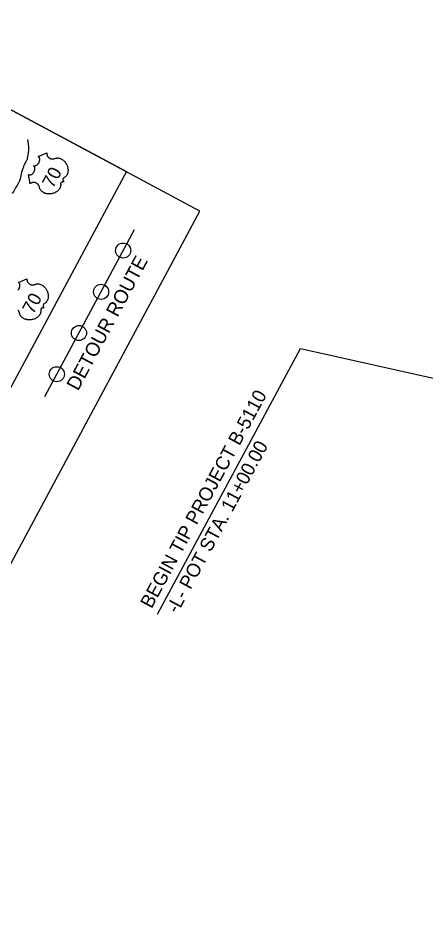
# Model space of a CAD drawing. Extents: x 1376167 to 1379209, y 761324 to 763997.
# Drawn here: x 1376772.1 to 1376981.7, y 762547.7 to 763014.5 of the extents above; entities that cross this region are included whole.
import ezdxf

# ---------------------------------------------------------------- set-up
doc = ezdxf.new("R2010")
doc.units = 0
for name, color, linetype in [('Default', 7, 'Continuous'), ('Old_Level_1', 7, 'Continuous'), ('Prop DSN Text', 7, 'Continuous')]:
    doc.layers.add(name, color=color, linetype=linetype)

msp = doc.modelspace()

# ---------------------------------------------------------------- linework, layer by layer
at = {"layer": 'Default'}
for points in [[(1376769.23, 762924.3), (1376769.71, 762925.09), (1376770.16, 762925.99), (1376770.78, 762927.08), (1376771.24, 762927.77), (1376772.3, 762929.6), (1376773, 762931.02), (1376773.32, 762931.96), (1376774.06, 762935.28), (1376774.5, 762936.86), (1376774.93, 762938.19), (1376775.09, 762938.63), (1376775.39, 762939.28), (1376776.44, 762941.22), (1376776.84, 762942.22), (1376776.93, 762942.61), (1376777.01, 762943.15), (1376777.33, 762945.03), (1376777.55, 762946.64), (1376777.51, 762948.32), (1376777.32, 762949.87), (1376777.12, 762952.07)], [(1376771.98, 762874.62), (1376772.11, 762874.77), (1376772.23, 762874.93), (1376772.35, 762875.09), (1376772.45, 762875.26), (1376772.54, 762875.4), (1376772.63, 762875.58), (1376772.71, 762875.75), (1376772.78, 762875.92), (1376772.85, 762876.13), (1376772.89, 762876.29), (1376772.95, 762876.52), (1376772.98, 762876.73), (1376772.99, 762876.92), (1376773, 762877.18), (1376772.98, 762877.4), (1376772.95, 762877.57), (1376772.9, 762877.78), (1376772.81, 762878), (1376772.74, 762878.14), (1376772.65, 762878.26), (1376772.56, 762878.38), (1376772.44, 762878.48), (1376772.34, 762878.56), (1376772.24, 762878.61), (1376776.6, 762880.49), (1376776.58, 762880.39), (1376776.58, 762880.17), (1376776.58, 762879.98), (1376776.62, 762879.67), (1376776.66, 762879.53), (1376776.69, 762879.39), (1376776.74, 762879.25), (1376776.79, 762879.12), (1376776.87, 762878.95), (1376776.96, 762878.8), (1376777.06, 762878.64), (1376777.15, 762878.51), (1376777.36, 762878.27), (1376777.5, 762878.13), (1376777.62, 762878.03), (1376777.9, 762877.83), (1376778.03, 762877.75), (1376778.17, 762877.67), (1376778.32, 762877.6), (1376778.46, 762877.54), (1376778.62, 762877.49), (1376778.76, 762877.44), (1376778.94, 762877.4), (1376779.15, 762877.36), (1376779.36, 762877.34), (1376779.73, 762877.34), (1376780.12, 762877.37), (1376780.36, 762877.42), (1376780.57, 762877.48), (1376780.85, 762877.59), (1376781, 762877.65), (1376781.19, 762877.71), (1376781.54, 762877.79), (1376781.7, 762877.81), (1376781.87, 762877.83), (1376782.04, 762877.83), (1376782.22, 762877.84), (1376782.37, 762877.83), (1376782.71, 762877.8), (1376783.03, 762877.74), (1376783.19, 762877.7), (1376783.55, 762877.59), (1376783.72, 762877.53), (1376784.04, 762877.38), (1376784.42, 762877.18), (1376784.77, 762876.96), (1376785.15, 762876.67), (1376785.37, 762876.48), (1376785.62, 762876.23), (1376785.82, 762876.02), (1376786.12, 762875.67), (1376786.32, 762875.39), (1376786.54, 762875.05), (1376786.67, 762874.83), (1376786.8, 762874.58), (1376786.94, 762874.28), (1376787.09, 762873.95), (1376787.22, 762873.57), (1376787.31, 762873.27), (1376787.4, 762872.89), (1376787.45, 762872.67), (1376787.5, 762872.36), (1376787.54, 762871.95), (1376787.55, 762871.56), (1376787.54, 762871.24), (1376787.52, 762870.96), (1376787.47, 762870.61), (1376787.35, 762870.06), (1376787.29, 762869.87), (1376787.21, 762869.64), (1376787.12, 762869.44), (1376787.03, 762869.24), (1376786.9, 762868.99), (1376786.74, 762868.74), (1376786.58, 762868.52), (1376786.39, 762868.3), (1376786.18, 762868.08), (1376785.96, 762867.9), (1376785.71, 762867.72), (1376785.24, 762867.45), (1376785.12, 762867.37), (1376785.06, 762867.31), (1376784.97, 762867.16), (1376784.93, 762867), (1376784.9, 762866.81), (1376784.9, 762866.7), (1376784.92, 762866.53), (1376784.94, 762866.4), (1376784.99, 762866.23), (1376785.04, 762866.11), (1376785.07, 762866.01), (1376785.19, 762865.8), (1376785.26, 762865.72), (1376785.34, 762865.62), (1376785.48, 762865.49), (1376785.25, 762865.55), (1376785.09, 762865.56), (1376784.93, 762865.55), (1376784.79, 762865.54), (1376784.6, 762865.49), (1376784.45, 762865.44), (1376784.28, 762865.37), (1376784.13, 762865.29), (1376784.02, 762865.21), (1376783.93, 762865.13), (1376783.84, 762865.03), (1376783.78, 762864.94), (1376783.74, 762864.86), (1376783.71, 762864.74), (1376783.73, 762864.53), (1376783.75, 762864.34), (1376783.77, 762864.14), (1376783.77, 762863.9), (1376783.76, 762863.74), (1376783.73, 762863.55), (1376783.7, 762863.33), (1376783.64, 762863.1), (1376783.57, 762862.87), (1376783.5, 762862.67), (1376783.41, 762862.47), (1376783.33, 762862.29), (1376783.23, 762862.11), (1376783.12, 762861.94), (1376783, 762861.76), (1376782.83, 762861.53), (1376782.67, 762861.35), (1376782.5, 762861.16), (1376782.31, 762860.98), (1376782.09, 762860.79), (1376781.8, 762860.56), (1376781.59, 762860.41), (1376781.22, 762860.19), (1376780.75, 762859.95), (1376780.37, 762859.78), (1376780.06, 762859.67), (1376779.58, 762859.53), (1376779.28, 762859.46), (1376778.75, 762859.37), (1376778.38, 762859.34), (1376778.12, 762859.32), (1376777.71, 762859.32), (1376777.46, 762859.33), (1376777.11, 762859.36), (1376776.79, 762859.41), (1376776.5, 762859.46), (1376776.31, 762859.5), (1376776, 762859.59), (1376775.78, 762859.66), (1376775.49, 762859.77), (1376775.19, 762859.9), (1376774.93, 762860.04), (1376774.71, 762860.16), (1376774.47, 762860.33), (1376774.22, 762860.52), (1376774.01, 762860.69), (1376773.87, 762860.83), (1376773.7, 762861.01), (1376773.52, 762861.22), (1376773.37, 762861.45), (1376773.24, 762861.65), (1376773.12, 762861.88), (1376773.02, 762862.09), (1376772.93, 762862.36), (1376772.86, 762862.62), (1376772.81, 762862.85), (1376772.73, 762863.14), (1376772.67, 762863.3), (1376772.58, 762863.5), (1376772.48, 762863.67), (1376772.39, 762863.82), (1376772.26, 762864.02), (1376772.15, 762864.15), (1376771.97, 762864.35)]]:
    msp.add_lwpolyline(points, dxfattribs=at)
msp.add_lwpolyline([(1376777.43, 762934.03), (1376777.57, 762933.97), (1376777.75, 762933.92), (1376777.84, 762933.9), (1376778.04, 762933.89), (1376778.29, 762933.91), (1376778.57, 762933.98), (1376778.83, 762934.09), (1376778.99, 762934.18), (1376779.23, 762934.34), (1376779.47, 762934.53), (1376779.7, 762934.77), (1376779.91, 762935.03), (1376780.12, 762935.32), (1376780.29, 762935.63), (1376780.45, 762935.98), (1376780.57, 762936.39), (1376780.62, 762936.58), (1376780.66, 762936.81), (1376780.68, 762937.03), (1376780.68, 762937.28), (1376780.66, 762937.49), (1376780.64, 762937.66), (1376780.57, 762937.92), (1376780.47, 762938.15), (1376780.4, 762938.26), (1376780.34, 762938.36), (1376780.18, 762938.53), (1376780.1, 762938.6), (1376779.93, 762938.71), (1376780.09, 762938.64), (1376780.19, 762938.61), (1376780.29, 762938.58), (1376780.41, 762938.57), (1376780.59, 762938.56), (1376780.75, 762938.58), (1376781, 762938.63), (1376781.13, 762938.68), (1376781.24, 762938.72), (1376781.51, 762938.86), (1376781.78, 762939.05), (1376781.91, 762939.15), (1376782.02, 762939.26), (1376782.16, 762939.39), (1376782.3, 762939.54), (1376782.42, 762939.7), (1376782.53, 762939.86), (1376782.64, 762940.03), (1376782.72, 762940.17), (1376782.82, 762940.35), (1376782.9, 762940.52), (1376782.97, 762940.7), (1376783.04, 762940.9), (1376783.08, 762941.07), (1376783.14, 762941.29), (1376783.17, 762941.5), (1376783.18, 762941.69), (1376783.19, 762941.95), (1376783.17, 762942.17), (1376783.14, 762942.34), (1376783.08, 762942.56), (1376783, 762942.78), (1376782.93, 762942.92), (1376782.84, 762943.04), (1376782.75, 762943.15), (1376782.63, 762943.26), (1376782.53, 762943.33), (1376782.43, 762943.39), (1376786.78, 762945.26), (1376786.77, 762945.17), (1376786.76, 762944.94), (1376786.77, 762944.76), (1376786.81, 762944.45), (1376786.84, 762944.3), (1376786.88, 762944.16), (1376786.93, 762944.02), (1376786.98, 762943.89), (1376787.06, 762943.73), (1376787.15, 762943.57), (1376787.25, 762943.41), (1376787.34, 762943.28), (1376787.55, 762943.04), (1376787.69, 762942.9), (1376787.81, 762942.8), (1376788.08, 762942.6), (1376788.22, 762942.52), (1376788.36, 762942.45), (1376788.5, 762942.38), (1376788.65, 762942.32), (1376788.81, 762942.26), (1376788.95, 762942.22), (1376789.13, 762942.17), (1376789.34, 762942.13), (1376789.55, 762942.11), (1376789.92, 762942.11), (1376790.31, 762942.15), (1376790.54, 762942.2), (1376790.76, 762942.26), (1376791.03, 762942.37), (1376791.19, 762942.42), (1376791.38, 762942.48), (1376791.73, 762942.56), (1376791.89, 762942.58), (1376792.06, 762942.6), (1376792.23, 762942.61), (1376792.41, 762942.61), (1376792.56, 762942.61), (1376792.9, 762942.57), (1376793.22, 762942.51), (1376793.38, 762942.47), (1376793.74, 762942.36), (1376793.91, 762942.3), (1376794.23, 762942.16), (1376794.61, 762941.95), (1376794.96, 762941.73), (1376795.34, 762941.44), (1376795.56, 762941.25), (1376795.8, 762941.01), (1376796.01, 762940.79), (1376796.31, 762940.44), (1376796.5, 762940.16), (1376796.73, 762939.82), (1376796.86, 762939.6), (1376796.99, 762939.35), (1376797.13, 762939.06), (1376797.28, 762938.72), (1376797.41, 762938.34), (1376797.5, 762938.04), (1376797.59, 762937.66), (1376797.64, 762937.44), (1376797.68, 762937.13), (1376797.72, 762936.72), (1376797.74, 762936.33), (1376797.73, 762936.01), (1376797.71, 762935.74), (1376797.66, 762935.39), (1376797.54, 762934.83), (1376797.48, 762934.64), (1376797.4, 762934.41), (1376797.31, 762934.21), (1376797.22, 762934.01), (1376797.09, 762933.76), (1376796.93, 762933.52), (1376796.77, 762933.3), (1376796.58, 762933.07), (1376796.37, 762932.86), (1376796.15, 762932.67), (1376795.9, 762932.49), (1376795.43, 762932.22), (1376795.31, 762932.14), (1376795.25, 762932.08), (1376795.16, 762931.93), (1376795.11, 762931.77), (1376795.09, 762931.59), (1376795.09, 762931.47), (1376795.11, 762931.31), (1376795.13, 762931.18), (1376795.18, 762931.01), (1376795.22, 762930.88), (1376795.26, 762930.79), (1376795.38, 762930.58), (1376795.44, 762930.49), (1376795.53, 762930.39), (1376795.67, 762930.26), (1376795.44, 762930.32), (1376795.27, 762930.33), (1376795.12, 762930.33), (1376794.98, 762930.31), (1376794.79, 762930.27), (1376794.63, 762930.22), (1376794.47, 762930.15), (1376794.32, 762930.06), (1376794.21, 762929.98), (1376794.12, 762929.91), (1376794.03, 762929.8), (1376793.97, 762929.71), (1376793.93, 762929.63), (1376793.89, 762929.51), (1376793.92, 762929.3), (1376793.94, 762929.11), (1376793.96, 762928.91), (1376793.95, 762928.68), (1376793.95, 762928.51), (1376793.92, 762928.32), (1376793.88, 762928.1), (1376793.83, 762927.87), (1376793.76, 762927.64), (1376793.69, 762927.45), (1376793.6, 762927.24), (1376793.52, 762927.06), (1376793.42, 762926.88), (1376793.31, 762926.72), (1376793.19, 762926.53), (1376793.02, 762926.3), (1376792.86, 762926.12), (1376792.69, 762925.94), (1376792.5, 762925.75), (1376792.28, 762925.56), (1376791.99, 762925.33), (1376791.77, 762925.19), (1376791.41, 762924.96), (1376790.94, 762924.72), (1376790.56, 762924.56), (1376790.25, 762924.45), (1376789.77, 762924.31), (1376789.46, 762924.24), (1376788.94, 762924.15), (1376788.57, 762924.11), (1376788.31, 762924.09), (1376787.9, 762924.09), (1376787.65, 762924.1), (1376787.3, 762924.13), (1376786.98, 762924.18), (1376786.69, 762924.23), (1376786.5, 762924.27), (1376786.19, 762924.36), (1376785.97, 762924.43), (1376785.68, 762924.54), (1376785.38, 762924.67), (1376785.11, 762924.81), (1376784.9, 762924.94), (1376784.65, 762925.1), (1376784.41, 762925.29), (1376784.2, 762925.47), (1376784.06, 762925.6), (1376783.89, 762925.78), (1376783.71, 762926), (1376783.55, 762926.22), (1376783.43, 762926.42), (1376783.31, 762926.65), (1376783.21, 762926.87), (1376783.12, 762927.13), (1376783.05, 762927.39), (1376783, 762927.62), (1376782.92, 762927.91), (1376782.86, 762928.07), (1376782.77, 762928.27), (1376782.67, 762928.44), (1376782.58, 762928.59), (1376782.45, 762928.79), (1376782.33, 762928.93), (1376782.15, 762929.12), (1376782.02, 762929.24), (1376781.84, 762929.39), (1376781.67, 762929.51), (1376781.44, 762929.65), (1376781.24, 762929.74), (1376781.01, 762929.84), (1376780.77, 762929.91), (1376780.55, 762929.96), (1376780.29, 762930), (1376780.09, 762930.01), (1376779.81, 762930), (1376779.54, 762929.97), (1376779.3, 762929.91), (1376779.08, 762929.84), (1376778.89, 762929.76), (1376778.73, 762929.68), (1376778.54, 762929.57), (1376778.37, 762929.45), (1376778.28, 762929.37)], close=True, dxfattribs=at)
at = {"layer": 'Old_Level_1'}
for points in [[(1376622.61, 762553.05), (1376345.79, 762701.47), (1376550.88, 763083.99), (1376827.7, 762935.57)], [(1376345.79, 762701.47), (1376660.36, 762532.81), (1376865.45, 762915.33), (1376550.88, 763083.99)]]:
    msp.add_lwpolyline(points, close=True, dxfattribs=at)
at = {"layer": 'Prop DSN Text'}
for p, q in [((1376785.82, 762819.91), (1376831.86, 762905.76)), ((1376843.67, 762708.05), (1376917.3, 762844.64)), ((1376917.3, 762844.64), (1377099.23, 762803.66))]:
    msp.add_line(p, q, dxfattribs=at)
for centre in [(1376826.08, 762894.98), (1376814.71, 762873.78), (1376803.34, 762852.58), (1376791.97, 762831.38)]:
    msp.add_circle(centre, 3.88, dxfattribs=at)

# ---------------------------------------------------------------- texts
at = {"layer": 'Default'}
for p in [(1376790.02, 762926.61), (1376779.83, 762861.83)]:
    msp.add_text('70', height=6.801, rotation=61.8015, dxfattribs=at).set_placement(p)
at = {"layer": 'Prop DSN Text'}
for s, height, rotation, p in [('DETOUR ROUTE', 7.1376, 61.8015, (1376802.87, 762822.47)), ('BEGIN TIP PROJECT B-5110', 7, 61.6702, (1376840.65, 762710.46)), ('-L- POT STA. 11+00.00', 7, 61.6702, (1376853.99, 762707.9))]:
    msp.add_text(s, height=height, rotation=rotation, dxfattribs=at).set_placement(p)

doc.saveas('drawing.dxf')
